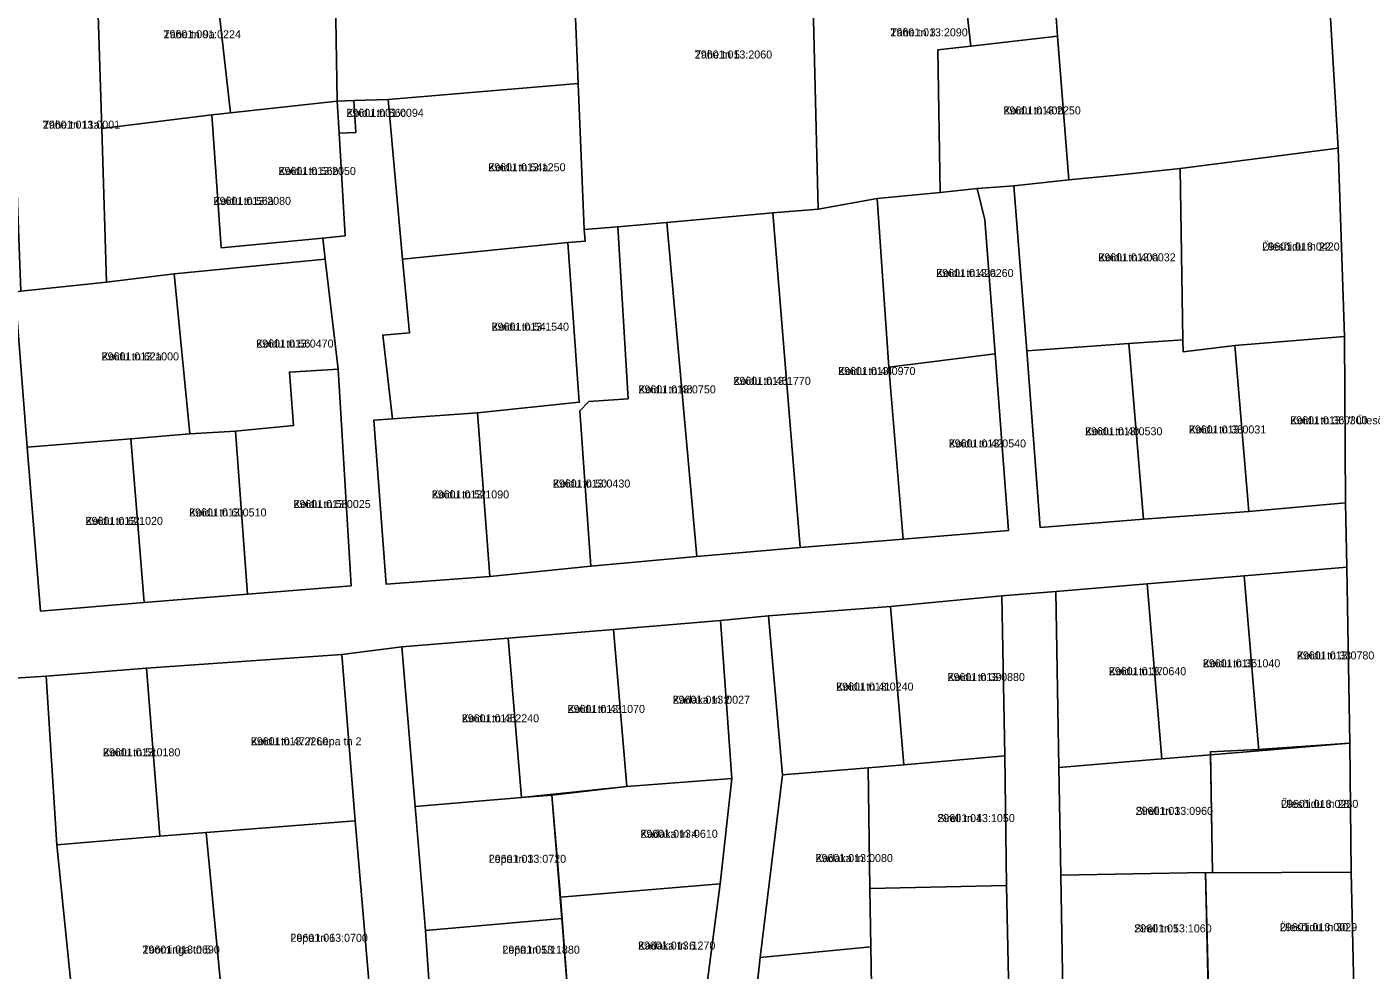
# Model space of a CAD drawing. Extents: x 518839 to 525192, y 6573164 to 6576561.
# Drawn here: x 523988.3 to 524240.2, y 6573831.7 to 6574008.4 of the extents above; entities that cross this region are included whole.
import ezdxf

# ---------------------------------------------------------------- set-up
doc = ezdxf.new("R2010")
doc.units = 0
for name, color, linetype in [('L_AADRESS', 7, 'Continuous'), ('PIIR', 7, 'Continuous'), ('TUNNUS', 7, 'Continuous')]:
    doc.layers.add(name, color=color, linetype=linetype)

msp = doc.modelspace()

# ---------------------------------------------------------------- linework, layer by layer
at = {"layer": 'PIIR'}
for points in [[(524230.53, 6574045.11), (524234.03, 6573985.67), (524204.44, 6573981.92), (524192.59, 6573980.67), (524183.58, 6573979.74), (524181.45, 6574006.66), (524180.98, 6574012.82), (524180.31, 6574040.22)], [(524161.43, 6574038.08), (524180.31, 6574040.22), (524180.98, 6574012.82), (524181.45, 6574006.66), (524165.16, 6574004.82)], [(524135.05, 6574035.08), (524161.43, 6574038.08), (524165.16, 6574004.82), (524159, 6574004.12), (524159.45, 6573977.4), (524147.65, 6573976.27), (524136.59, 6573974.27)], [(524092.69, 6573970.46), (524091.59, 6573997.82), (524090.29, 6574030.24), (524135.05, 6574035.08), (524136.59, 6573974.27), (524128.09, 6573973.58), (524108.18, 6573971.79), (524099.02, 6573970.97)], [(524046.41, 6573994.52), (524045.92, 6574025.3), (524090.29, 6574030.24), (524091.59, 6573997.82), (524055.99, 6573994.8), (524049.57, 6573994.61)], [(524026.43, 6573992.3), (524022.98, 6574022.77), (524045.92, 6574025.3), (524046.41, 6573994.52)], [(524001.33, 6574020.4), (524022.98, 6574022.77), (524026.43, 6573992.3), (524022.94, 6573991.92), (524002.35, 6573989.41)], [(523986.5, 6573975.48), (523986.02, 6573991.28), (523980.25, 6573991.75), (523979.32, 6574018.22), (524001.33, 6574020.4), (524002.35, 6573989.41), (524003.19, 6573960.61), (523987.11, 6573958.88)], [(524159.45, 6573977.4), (524159, 6574004.12), (524165.16, 6574004.82), (524181.45, 6574006.66), (524183.58, 6573979.74), (524173.22, 6573978.67), (524166.39, 6573978.16)], [(524055.99, 6573994.8), (524091.59, 6573997.82), (524092.69, 6573970.46), (524092.89, 6573968.25), (524089.64, 6573968.02), (524058.7, 6573964.92)], [(524022.94, 6573991.92), (524026.43, 6573992.3), (524046.41, 6573994.52), (524046.77, 6573988.53), (524047.92, 6573969.27), (524043.72, 6573968.86), (524024.71, 6573967.01)], [(524046.77, 6573988.53), (524046.41, 6573994.52), (524049.57, 6573994.61), (524049.92, 6573988.62)], [(524003.19, 6573960.61), (524002.35, 6573989.41), (524022.94, 6573991.92), (524024.71, 6573967.01), (524043.72, 6573968.86), (524044.19, 6573964.89), (524024.86, 6573963.02), (524015.9, 6573962.16)], [(524214.64, 6573948.74), (524204.96, 6573947.54), (524204.93, 6573949.78), (524204.44, 6573981.92), (524234.03, 6573985.67), (524235.19, 6573950.42)], [(524173.22, 6573978.67), (524183.58, 6573979.74), (524192.59, 6573980.67), (524204.44, 6573981.92), (524204.93, 6573949.78), (524194.81, 6573949.07), (524175.65, 6573947.72)], [(524147.65, 6573976.27), (524159.45, 6573977.4), (524166.39, 6573978.16), (524167.8, 6573972.26), (524169.74, 6573947.18), (524149.79, 6573944.69)], [(524128.09, 6573973.58), (524136.59, 6573974.27), (524147.65, 6573976.27), (524149.79, 6573944.69), (524152.53, 6573912.45), (524133.19, 6573910.86)], [(524108.18, 6573971.79), (524128.09, 6573973.58), (524133.19, 6573910.86), (524113.86, 6573909.2)], [(524075.02, 6573905.45), (524072.75, 6573936.12), (524091.79, 6573938.1), (524089.64, 6573968.02), (524092.89, 6573968.25), (524092.69, 6573970.46), (524099.02, 6573970.97), (524100.96, 6573938.76), (524093.58, 6573938.23), (524091.91, 6573936.46), (524093.99, 6573907.35)], [(524091.91, 6573936.46), (524093.58, 6573938.23), (524100.96, 6573938.76), (524099.02, 6573970.97), (524108.18, 6573971.79), (524113.86, 6573909.2), (524093.99, 6573907.35)], [(524056.82, 6573934.98), (524054.98, 6573950.67), (524059.96, 6573951.08), (524058.7, 6573964.92), (524089.64, 6573968.02), (524091.79, 6573938.1), (524072.75, 6573936.12)], [(524018.83, 6573932.16), (524015.9, 6573962.16), (524024.86, 6573963.02), (524044.19, 6573964.89), (524046.61, 6573944.26), (524037.48, 6573943.74), (524038.26, 6573933.74), (524027.38, 6573932.64)], [(523986.71, 6573950.55), (523986.06, 6573958.7), (523987.11, 6573958.88), (524003.19, 6573960.61), (524015.9, 6573962.16), (524018.83, 6573932.16), (524007.73, 6573931.26), (523988.32, 6573929.69)], [(524194.81, 6573949.07), (524204.93, 6573949.78), (524204.96, 6573947.54), (524214.64, 6573948.74), (524217.28, 6573917.64), (524197.52, 6573916.17)], [(524214.64, 6573948.74), (524235.19, 6573950.42), (524235.43, 6573919.25), (524217.28, 6573917.64)], [(524149.79, 6573944.69), (524169.74, 6573947.18), (524172.27, 6573914.07), (524152.53, 6573912.45)], [(524175.65, 6573947.72), (524194.81, 6573949.07), (524197.52, 6573916.17), (524178.17, 6573914.63)], [(524049.03, 6573903.68), (524029.64, 6573902.11), (524027.38, 6573932.64), (524038.26, 6573933.74), (524037.48, 6573943.74), (524046.61, 6573944.26)], [(524053.28, 6573934.73), (524056.82, 6573934.98), (524072.75, 6573936.12), (524075.02, 6573905.45), (524055.61, 6573903.99)], [(524010.23, 6573900.54), (524007.73, 6573931.26), (524018.83, 6573932.16), (524027.38, 6573932.64), (524029.64, 6573902.11)], [(523990.82, 6573898.95), (523988.32, 6573929.69), (524007.73, 6573931.26), (524010.23, 6573900.54)], [(524235.66, 6573907.19), (524236.22, 6573874.23), (524219.14, 6573872.8), (524216.39, 6573905.57)], [(524198.21, 6573904.04), (524200.96, 6573871.27), (524181.69, 6573869.65), (524181.14, 6573902.62)], [(524216.39, 6573905.57), (524219.14, 6573872.8), (524210.09, 6573872.04), (524200.96, 6573871.27), (524198.21, 6573904.04)], [(524150.1, 6573899.79), (524171.01, 6573901.81), (524171.54, 6573871.84), (524152.62, 6573870.13)], [(524171.01, 6573901.81), (524181.14, 6573902.62), (524181.69, 6573869.65), (524182.03, 6573849.5), (524182.4, 6573827.52), (524182.77, 6573805.55), (524183.22, 6573781.74), (524183.79, 6573748.78), (524173.3, 6573748.03), (524173.42, 6573778.34), (524172.85, 6573800.9), (524171.9, 6573847.55), (524171.54, 6573871.84)], [(524127.26, 6573898.06), (524150.1, 6573899.79), (524152.62, 6573870.13), (524145.94, 6573869.59), (524129.88, 6573868.3)], [(524098.2, 6573895.51), (524118.3, 6573897.21), (524120.39, 6573867.6), (524100.74, 6573866.1)], [(524118.3, 6573897.21), (524127.26, 6573898.06), (524129.88, 6573868.3), (524125.71, 6573834.07), (524122.82, 6573807.59), (524119.88, 6573781.09), (524121.33, 6573743.05), (524110.68, 6573742.36), (524108.59, 6573772.41), (524110.09, 6573782.88), (524110.84, 6573788.98), (524115.19, 6573825.02), (524118.19, 6573847.87), (524120.39, 6573867.6)], [(524078.48, 6573893.9), (524080.99, 6573864.01), (524061.06, 6573862.34), (524058.55, 6573892.23)], [(524098.2, 6573895.51), (524100.74, 6573866.1), (524080.99, 6573864.01), (524078.48, 6573893.9)], [(524047.28, 6573890.84), (524058.55, 6573892.23), (524061.06, 6573862.34), (524063.01, 6573839.09), (524063.75, 6573828.06), (524066.74, 6573792.48), (524068.87, 6573769.65), (524070.8, 6573740.41), (524061.06, 6573740.01), (524058.24, 6573773.57), (524057.22, 6573773.49), (524055.17, 6573794.96), (524053.5, 6573816.5), (524049.82, 6573859.68)], [(524013.16, 6573856.78), (524010.68, 6573888.24), (524047.28, 6573890.84), (524049.82, 6573859.68), (524021.85, 6573857.47)], [(523979.96, 6573886.04), (523991.91, 6573886.74), (523993.87, 6573855.18), (523998.29, 6573812.14), (523999.71, 6573790.43), (524001.71, 6573769.87), (524004.3, 6573740.13), (523991.73, 6573738.64), (523989.14, 6573774.8), (523987.31, 6573795.12), (523985.77, 6573815.38), (523983.8, 6573835.68), (523982.65, 6573856.32)], [(523991.91, 6573886.74), (524010.68, 6573888.24), (524013.16, 6573856.78), (523993.87, 6573855.18)], [(524236.22, 6573874.23), (524236.46, 6573850.03), (524210.49, 6573849.92), (524210.1, 6573872.61), (524218.95, 6573873.01)], [(524145.94, 6573869.59), (524152.62, 6573870.13), (524171.54, 6573871.84), (524171.9, 6573847.55), (524146.27, 6573847)], [(524181.69, 6573869.65), (524200.96, 6573871.27), (524210.09, 6573872.04), (524210.49, 6573849.92), (524209.16, 6573849.98), (524182.03, 6573849.5)], [(524129.88, 6573868.3), (524145.94, 6573869.59), (524146.27, 6573847), (524146.43, 6573836.06), (524125.71, 6573834.07)], [(524118.19, 6573847.87), (524088.29, 6573845.35), (524086.68, 6573864.49), (524100.74, 6573866.1), (524120.39, 6573867.6)], [(524061.06, 6573862.34), (524080.99, 6573864.01), (524086.68, 6573864.49), (524088.56, 6573841.38), (524063.01, 6573839.09)], [(524021.85, 6573857.47), (524049.82, 6573859.68), (524053.5, 6573816.5), (524025.99, 6573814.33)], [(523993.87, 6573855.18), (524013.16, 6573856.78), (524021.85, 6573857.47), (524025.99, 6573814.33), (523998.29, 6573812.14)], [(524182.03, 6573849.5), (524209.16, 6573849.98), (524209.7, 6573827.98), (524182.4, 6573827.52)], [(524209.16, 6573849.98), (524210.49, 6573849.92), (524236.46, 6573850.03), (524236.99, 6573828.15), (524209.69, 6573827.93)], [(524115.19, 6573825.02), (524089.98, 6573823.21), (524088.29, 6573845.35), (524118.19, 6573847.87)], [(524146.27, 6573847), (524171.9, 6573847.55), (524172.85, 6573800.9), (524147.23, 6573800.32), (524146.85, 6573810.16), (524146.43, 6573836.06)], [(524063.01, 6573839.09), (524088.56, 6573841.38), (524089.98, 6573823.21), (524091.79, 6573799.67), (524081.38, 6573798.86), (524079.42, 6573829.3), (524063.75, 6573828.06)], [(524125.71, 6573834.07), (524146.43, 6573836.06), (524146.85, 6573810.16), (524122.82, 6573807.59)]]:
    msp.add_lwpolyline(points, close=True, dxfattribs=at)
for points in [[(524239.31, 6573619.05), (524238.88, 6573659.13), (524239.02, 6573710.03), (524238.3, 6573740.81), (524238.21, 6573753.11), (524237.58, 6573786.23), (524237.36, 6573806.47), (524236.99, 6573828.15), (524236.46, 6573850.03), (524236.22, 6573874.23), (524235.66, 6573907.19), (524235.43, 6573919.25), (524235.19, 6573950.42), (524234.03, 6573985.67), (524230.53, 6574045.11)], [(523986.71, 6573950.55), (523988.32, 6573929.69), (523990.82, 6573898.95), (524010.23, 6573900.54), (524029.64, 6573902.11), (524049.03, 6573903.68), (524046.61, 6573944.26), (524044.19, 6573964.89), (524043.72, 6573968.86), (524047.92, 6573969.27), (524046.77, 6573988.53), (524049.92, 6573988.62), (524049.57, 6573994.61), (524055.99, 6573994.8), (524058.7, 6573964.92), (524059.96, 6573951.08), (524054.98, 6573950.67), (524056.82, 6573934.98), (524053.28, 6573934.73), (524055.61, 6573903.99), (524075.02, 6573905.45), (524093.99, 6573907.35), (524113.86, 6573909.2), (524133.19, 6573910.86), (524152.53, 6573912.45), (524172.27, 6573914.07), (524169.74, 6573947.18), (524167.8, 6573972.26), (524166.39, 6573978.16), (524173.22, 6573978.67), (524175.65, 6573947.72), (524178.17, 6573914.63), (524197.52, 6573916.17), (524217.28, 6573917.64), (524235.43, 6573919.25), (524235.66, 6573907.19), (524216.39, 6573905.57), (524198.21, 6573904.04), (524181.14, 6573902.62), (524171.01, 6573901.81), (524150.1, 6573899.79), (524127.26, 6573898.06), (524118.3, 6573897.21), (524098.2, 6573895.51), (524078.48, 6573893.9), (524058.55, 6573892.23), (524047.28, 6573890.84), (524010.68, 6573888.24), (523991.91, 6573886.74), (523979.96, 6573886.04)]]:
    msp.add_lwpolyline(points, dxfattribs=at)

# ---------------------------------------------------------------- texts
at = {"layer": 'L_AADRESS'}
for s, p in [('Tähe tn 9a', (524013.88, 6574006.29)), ('Tähe tn 3', (524150.1, 6574006.65)), ('Tähe tn 5', (524113.44, 6574002.5)), ('Koidu tn 56c', (524048.16, 6573991.57)), ('Koidu tn 40b', (524171.29, 6573992.02)), ('Tähe tn 11a', (523991.25, 6573989.36)), ('Koidu tn 56b', (524035.43, 6573980.68)), ('Koidu tn 54a', (524074.73, 6573981.37)), ('Koidu tn 56a', (524023.27, 6573975.07)), ('Ülesõidu tn 22', (524219.81, 6573966.52)), ('Koidu tn 40a', (524189.07, 6573964.49)), ('Koidu tn 42a', (524158.7, 6573961.56)), ('Koidu tn 54', (524075.37, 6573951.5)), ('Koidu tn 56', (524031.25, 6573948.34)), ('Koidu tn 62a', (524002.28, 6573945.93)), ('Koidu tn 44', (524140.31, 6573943.19)), ('Koidu tn 46', (524120.68, 6573941.35)), ('Koidu tn 48', (524102.88, 6573939.75)), ('Koidu tn 36 // Ülesõidu tn 24', (524225.04, 6573933.96)), ('Koidu tn 40', (524186.59, 6573931.9)), ('Koidu tn 38', (524206.05, 6573932.24)), ('Koidu tn 42', (524161.03, 6573929.62)), ('Koidu tn 52', (524064.15, 6573920.07)), ('Koidu tn 50', (524086.86, 6573922.11)), ('Koidu tn 58', (524038.21, 6573918.27)), ('Koidu tn 62', (523999.27, 6573915.11)), ('Koidu tn 60', (524018.68, 6573916.69)), ('Koidu tn 33', (524226.3, 6573889.9)), ('Koidu tn 35', (524208.68, 6573888.42)), ('Koidu tn 39', (524160.82, 6573885.85)), ('Koidu tn 37', (524191.05, 6573886.94)), ('Koidu tn 41', (524139.94, 6573884.06)), ('Koidu tn 43', (524089.61, 6573879.87)), ('Kadaka tn 2', (524109.3, 6573881.6)), ('Koidu tn 45', (524069.77, 6573878.12)), ('Koidu tn 47 // Lepa tn 2', (524030.24, 6573873.81)), ('Koidu tn 51', (524002.53, 6573871.74)), ('Ülesõidu tn 28', (524223.31, 6573862.08)), ('Sireli tn 4', (524158.91, 6573859.42)), ('Sireli tn 3', (524196.07, 6573860.77)), ('Kadaka tn 4', (524103.25, 6573856.48)), ('Kadaka tn 1', (524136.07, 6573851.93)), ('Lepa tn 3', (524074.83, 6573851.79)), ('Lepa tn 6', (524037.68, 6573836.99)), ('Sireli tn 5', (524195.82, 6573838.75)), ('Ülesõidu tn 30', (524223.08, 6573838.98)), ('Toominga tn 5', (524009.93, 6573834.79)), ('Lepa tn 5/1', (524077.4, 6573834.76)), ('Kadaka tn 6', (524102.81, 6573835.54))]:
    msp.add_text(s, height=1.5, dxfattribs=at).set_placement(p)
at = {"layer": 'TUNNUS'}
for s, p in [('29601:001:0224', (524013.88, 6574006.29)), ('29601:013:2090', (524150.1, 6574006.65)), ('29601:013:2060', (524113.44, 6574002.5)), ('29601:001:0094', (524048.16, 6573991.57)), ('29601:013:2250', (524171.29, 6573992.02)), ('29601:013:0001', (523991.25, 6573989.36)), ('29601:013:2050', (524035.43, 6573980.68)), ('29601:013:1250', (524074.73, 6573981.37)), ('29601:013:2080', (524023.27, 6573975.07)), ('29601:013:0420', (524219.81, 6573966.52)), ('29601:013:0032', (524189.07, 6573964.49)), ('29601:013:0260', (524158.7, 6573961.56)), ('29601:013:1540', (524075.37, 6573951.5)), ('29601:013:0470', (524031.25, 6573948.34)), ('29601:013:1000', (524002.28, 6573945.93)), ('29601:013:0970', (524140.31, 6573943.19)), ('29601:013:1770', (524120.68, 6573941.35)), ('29601:013:0750', (524102.88, 6573939.75)), ('29601:013:0300', (524225.04, 6573933.96)), ('29601:013:0530', (524186.59, 6573931.9)), ('29601:013:0031', (524206.05, 6573932.24)), ('29601:013:0540', (524161.03, 6573929.62)), ('29601:013:1090', (524064.15, 6573920.07)), ('29601:013:0430', (524086.86, 6573922.11)), ('29601:013:0025', (524038.21, 6573918.27)), ('29601:013:1020', (523999.27, 6573915.11)), ('29601:013:0510', (524018.68, 6573916.69)), ('29601:013:0780', (524226.3, 6573889.9)), ('29601:013:1040', (524208.68, 6573888.42)), ('29601:013:0880', (524160.82, 6573885.85)), ('29601:013:0640', (524191.05, 6573886.94)), ('29601:013:0240', (524139.94, 6573884.06)), ('29601:013:1070', (524089.61, 6573879.87)), ('29601:013:0027', (524109.3, 6573881.6)), ('29601:013:2240', (524069.77, 6573878.12)), ('29601:013:2260', (524030.24, 6573873.81)), ('29601:013:0180', (524002.53, 6573871.74)), ('29601:013:0230', (524223.31, 6573862.08)), ('29601:013:0960', (524196.07, 6573860.77)), ('29601:013:1050', (524158.91, 6573859.42)), ('29601:013:0610', (524103.25, 6573856.48)), ('29601:013:0080', (524136.07, 6573851.93)), ('29601:013:0720', (524074.83, 6573851.79)), ('29601:013:0700', (524037.68, 6573836.99)), ('29601:013:1060', (524195.82, 6573838.75)), ('29601:013:0029', (524223.08, 6573838.98)), ('29601:013:0690', (524009.93, 6573834.79)), ('29601:013:1880', (524077.4, 6573834.76)), ('29601:013:1270', (524102.81, 6573835.54))]:
    msp.add_text(s, height=1.5, dxfattribs=at).set_placement(p)

doc.saveas('drawing.dxf')
